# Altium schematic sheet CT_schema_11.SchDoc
size 742 x 377 mm
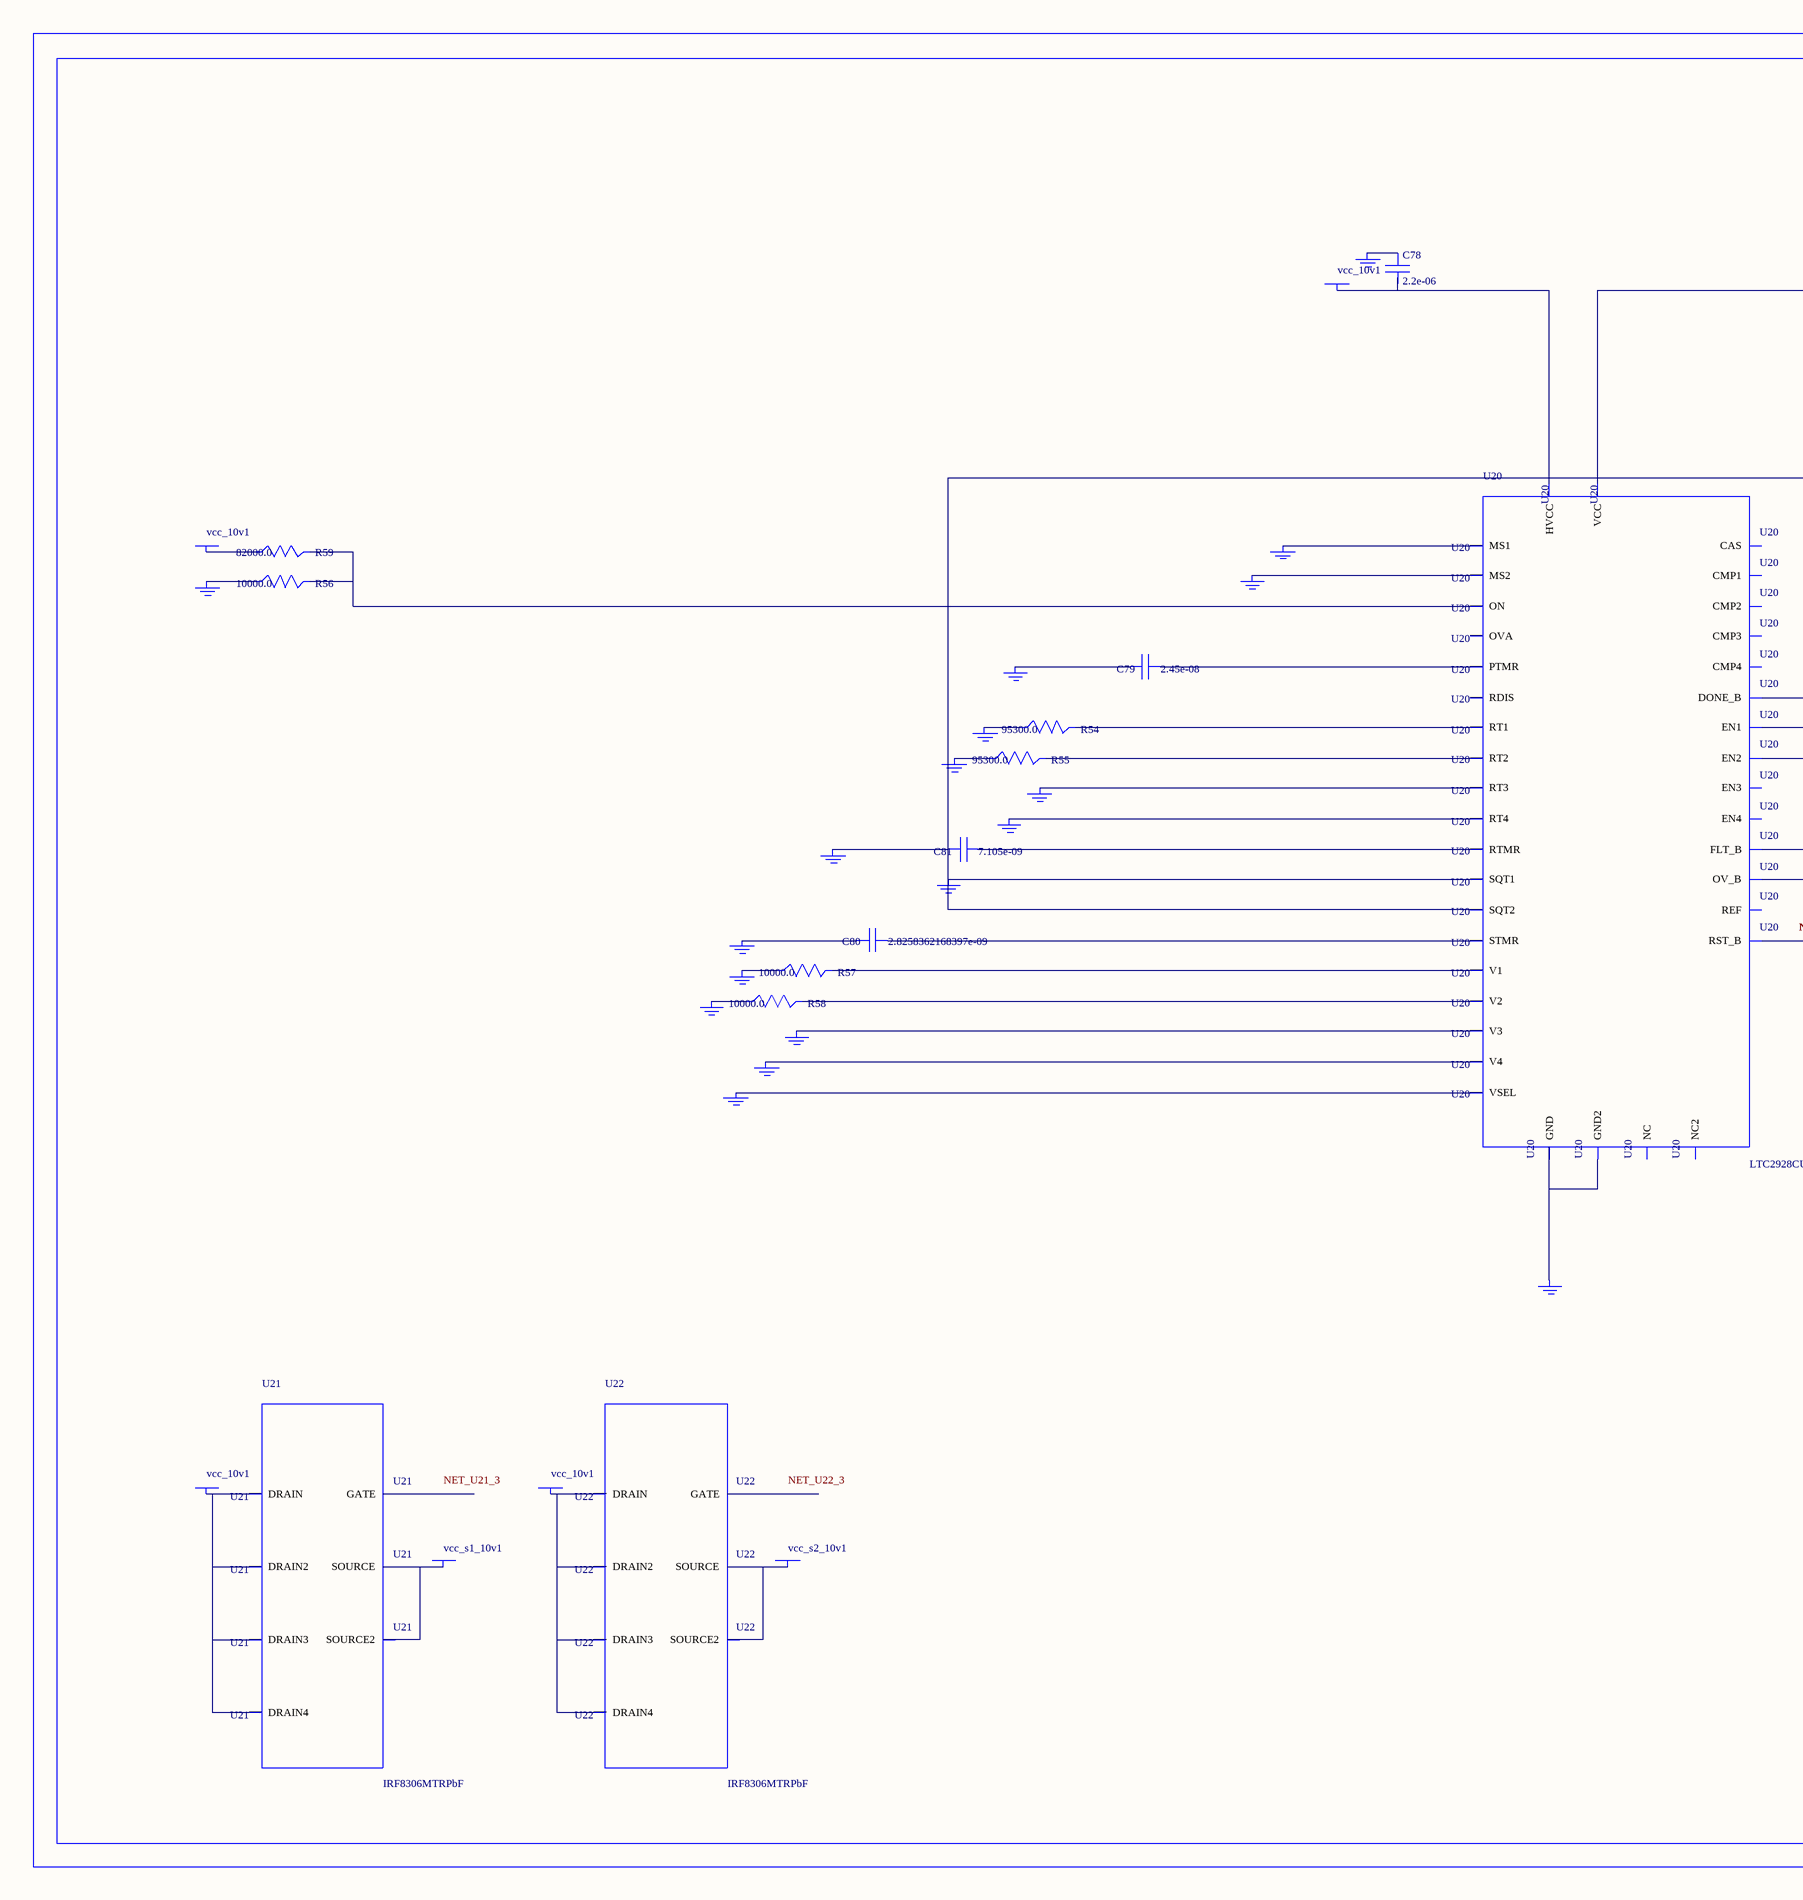
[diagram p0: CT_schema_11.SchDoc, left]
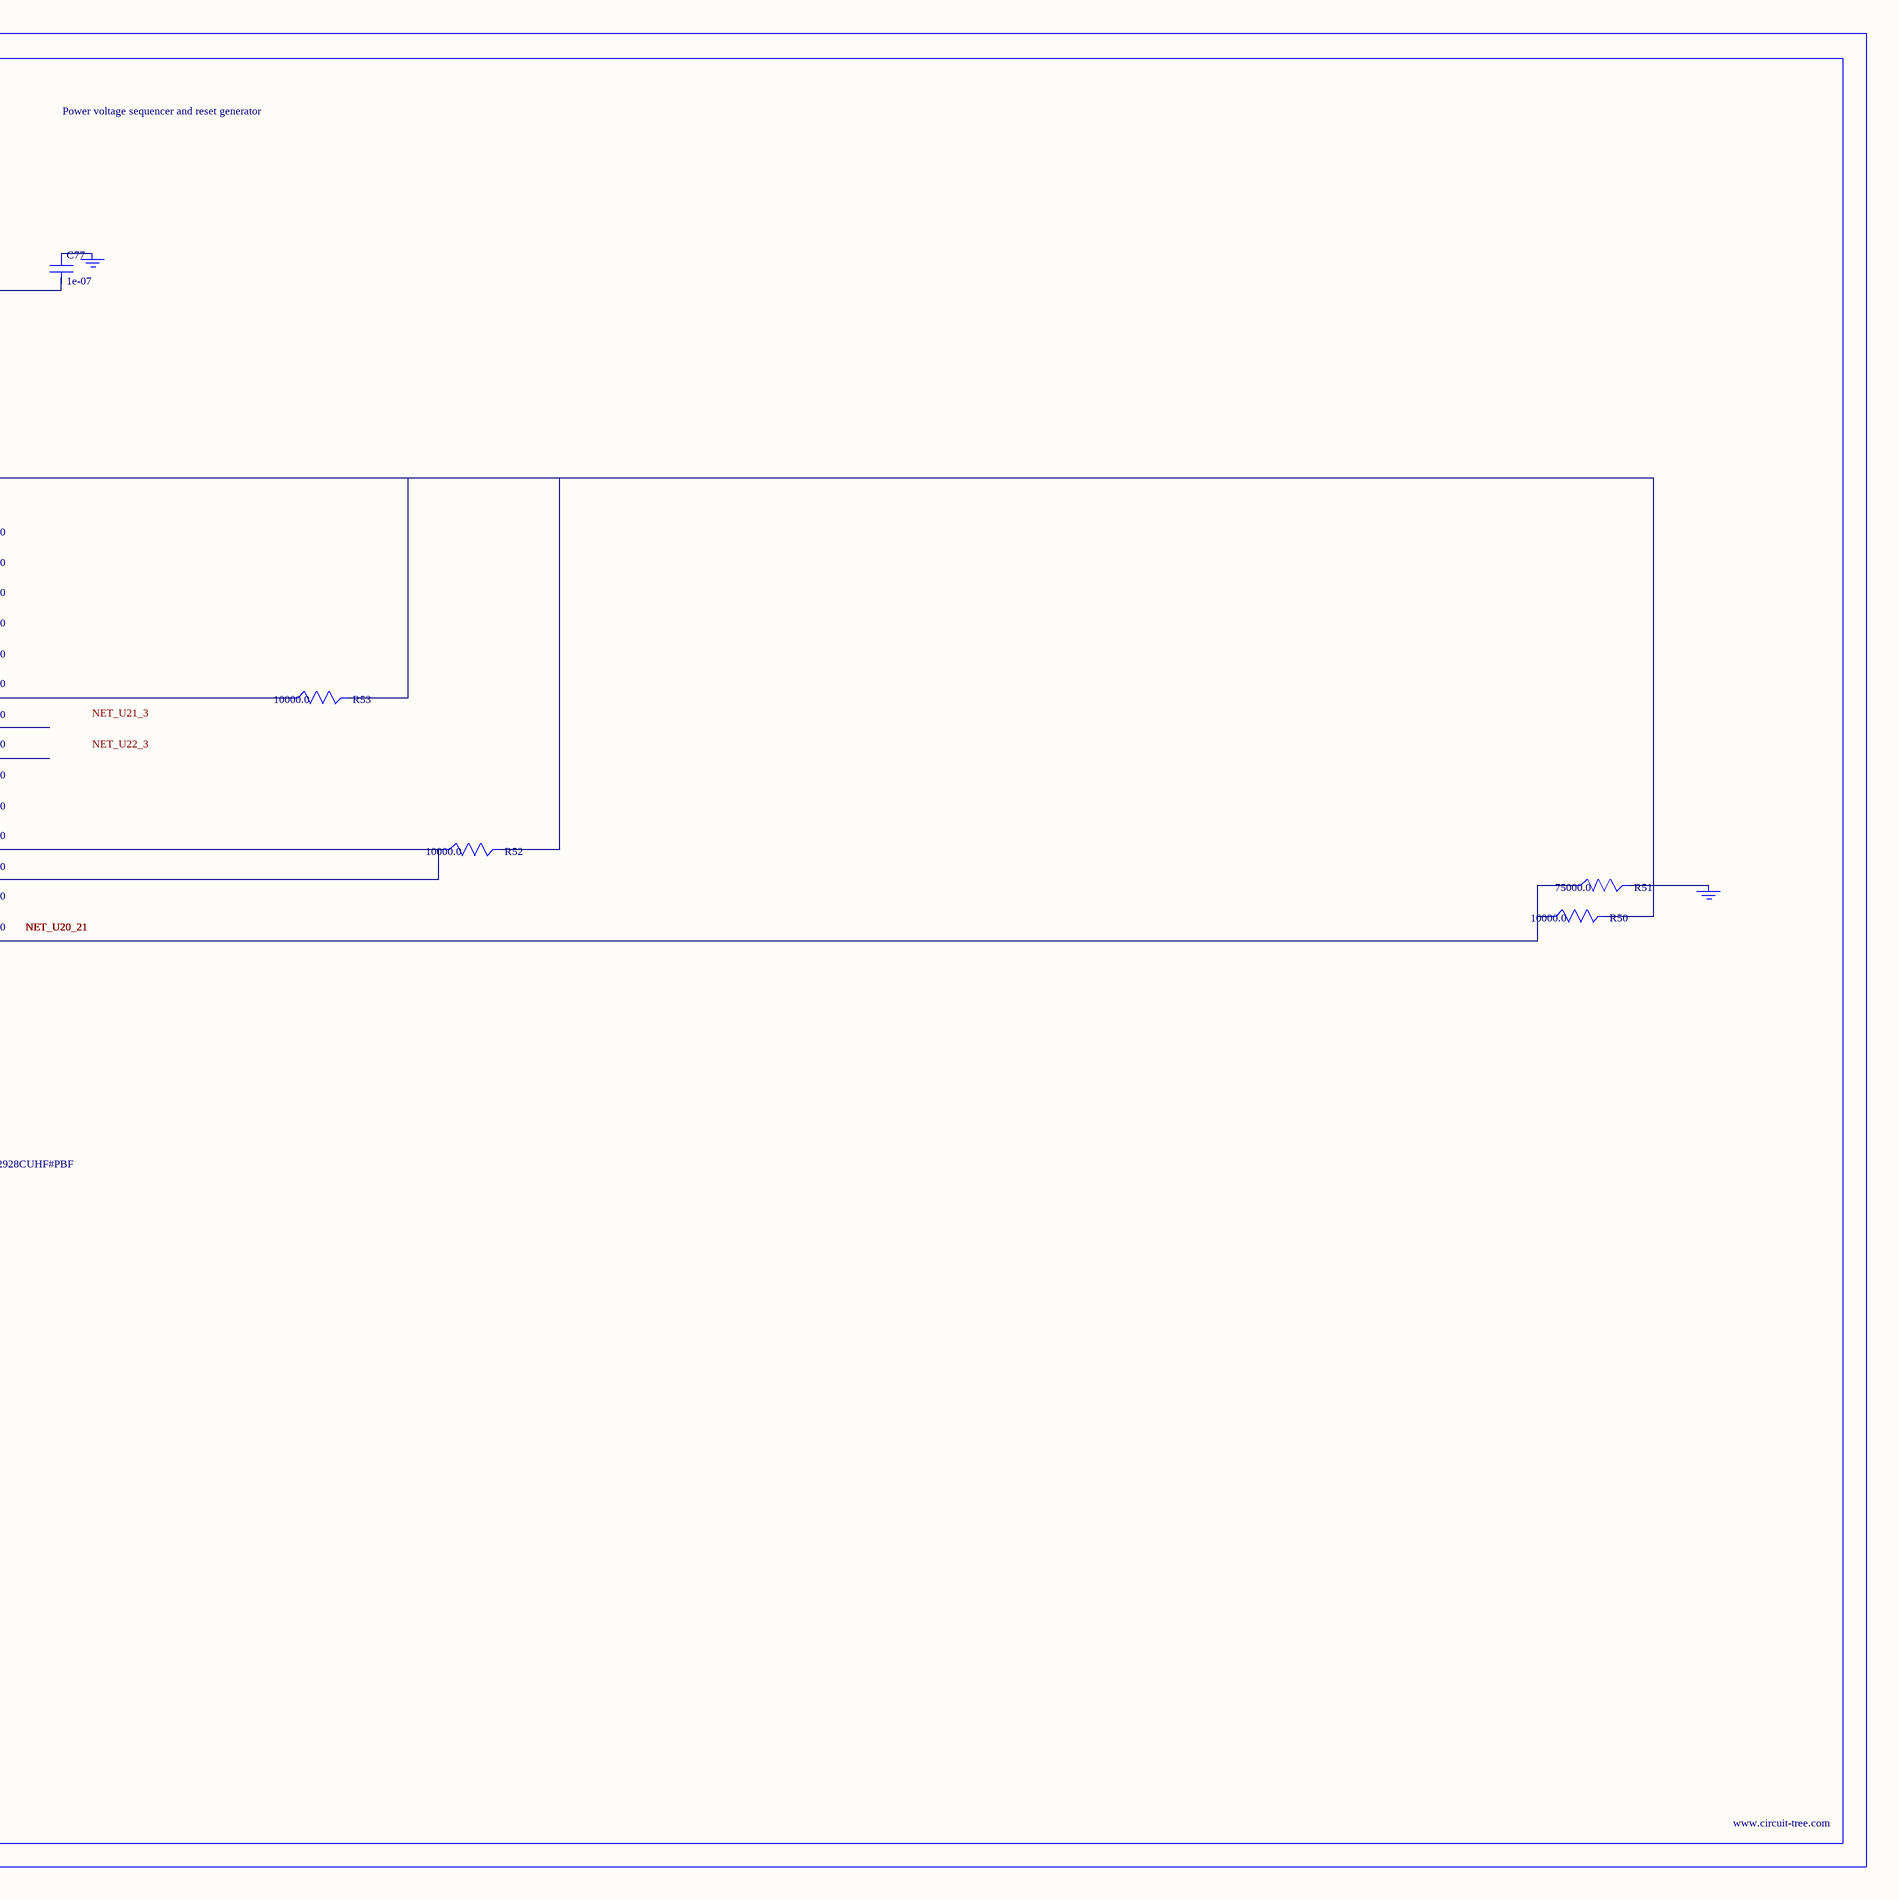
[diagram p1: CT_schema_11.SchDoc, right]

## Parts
BORDER10  (no value)
C77  1e-07  [C0402]
C78  2.2e-06  [C0603]
C79  2.45e-08  [R0603]
C80  2.8258362168397e-09  [R0603]
C81  7.105e-09  [R0603]
GND_INSTANCE_10_0  (no value)
GND_INSTANCE_10_1  (no value)
GND_INSTANCE_10_2  (no value)
GND_INSTANCE_10_3  (no value)
GND_INSTANCE_10_4  (no value)
GND_INSTANCE_10_5  (no value)
GND_INSTANCE_10_6  (no value)
GND_INSTANCE_10_7  (no value)
GND_INSTANCE_10_8  (no value)
GND_INSTANCE_10_9  (no value)
GND_INSTANCE_10_10  (no value)
GND_INSTANCE_10_11  (no value)
GND_INSTANCE_10_12  (no value)
GND_INSTANCE_10_13  (no value)
GND_INSTANCE_10_14  (no value)
GND_INSTANCE_10_15  (no value)
GND_INSTANCE_10_16  (no value)
GND_INSTANCE_10_17  (no value)
GND_INSTANCE_10_18  (no value)
GND_INSTANCE_10_19  (no value)
POWER_INSTANCE_10_0  vcc_10v1
POWER_INSTANCE_10_1  vcc_10v1
POWER_INSTANCE_10_2  vcc_10v1
POWER_INSTANCE_10_3  vcc_s1_10v1
POWER_INSTANCE_10_4  vcc_10v1
POWER_INSTANCE_10_5  vcc_s2_10v1
R50  10000.0  [R0603]
R51  75000.0  [R0603]
R52  10000.0  [R0603]
R53  10000.0  [R0603]
R54  95300.0  [R0603]
R55  95300.0  [R0603]
R56  10000.0  [R0603]
R57  10000.0  [R0603]
R58  10000.0  [R0603]
R59  82000.0  [R0603]
U20  LTC2928CUHF#PBF  [QFN-38_UHF]
U21  IRF8306MTRPbF  [IRF8306MTRPBF]
U22  IRF8306MTRPbF  [IRF8306MTRPBF]

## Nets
NetC77_1: C77.1 GND_INSTANCE_10_10.0(GND)
NetC77_2: C77.2 C81.2 GND_INSTANCE_10_5.0(GND) GND_INSTANCE_10_15.0(GND) R50.2 R52.2 R53.2 U20.10(SQT1) U20.11(SQT2) U20.22(VCC)
NetC78_1: C78.1 GND_INSTANCE_10_11.0(GND)
NetC78_2: C78.2 POWER_INSTANCE_10_1.0(PWR) U20.23(HVCC)
NetC79_1: C79.1 U20.27(PTMR)
NetC79_2: C79.2 GND_INSTANCE_10_14.0(GND)
NetC80_1: C80.1 U20.26(STMR)
NetC80_2: C80.2 GND_INSTANCE_10_13.0(GND)
NetC81_1: C81.1 U20.28(RTMR)
NetGND_INSTANCE_10_0_0: GND_INSTANCE_10_0.0(GND) R57.1
NetGND_INSTANCE_10_1_0: GND_INSTANCE_10_1.0(GND) R54.1
NetGND_INSTANCE_10_2_0: GND_INSTANCE_10_2.0(GND) R55.1
NetGND_INSTANCE_10_3_0: GND_INSTANCE_10_3.0(GND) U20.8(RT3)
NetGND_INSTANCE_10_4_0: GND_INSTANCE_10_4.0(GND) U20.9(RT4)
NetGND_INSTANCE_10_6_0: GND_INSTANCE_10_6.0(GND) U20.12(MS1)
NetGND_INSTANCE_10_7_0: GND_INSTANCE_10_7.0(GND) U20.13(MS2)
NetGND_INSTANCE_10_8_0: GND_INSTANCE_10_8.0(GND) R56.1
NetGND_INSTANCE_10_9_0: GND_INSTANCE_10_9.0(GND) R51.2
NetGND_INSTANCE_10_12_0: GND_INSTANCE_10_12.0(GND) U20.25(VSEL)
NetGND_INSTANCE_10_16_0: GND_INSTANCE_10_16.0(GND) U20.30(V4)
NetGND_INSTANCE_10_17_0: GND_INSTANCE_10_17.0(GND) U20.32(V3)
NetGND_INSTANCE_10_18_0: GND_INSTANCE_10_18.0(GND) R58.1
NetGND_INSTANCE_10_19_0: GND_INSTANCE_10_19.0(GND) U20.24(GND) U20.39(GND2)
NetPOWER_INSTANCE_10_0_0: POWER_INSTANCE_10_0.0(PWR) R59.1
NetPOWER_INSTANCE_10_2_0: POWER_INSTANCE_10_2.0(PWR) U21.1(DRAIN) U21.2(DRAIN2) U21.6(DRAIN3) U21.7(DRAIN4)
NetPOWER_INSTANCE_10_3_0: POWER_INSTANCE_10_3.0(PWR) U21.4(SOURCE) U21.5(SOURCE2)
NetPOWER_INSTANCE_10_4_0: POWER_INSTANCE_10_4.0(PWR) U22.1(DRAIN) U22.2(DRAIN2) U22.6(DRAIN3) U22.7(DRAIN4)
NetPOWER_INSTANCE_10_5_0: POWER_INSTANCE_10_5.0(PWR) U22.4(SOURCE) U22.5(SOURCE2)
NetR50_1: R50.1 R51.1 U20.21(RST_B)
NetR52_1: R52.1 U20.19(FLT_B) U20.20(OV_B)
NetR53_1: R53.1 U20.18(DONE_B)
NetR54_2: R54.2 U20.6(RT1)
NetR55_2: R55.2 U20.7(RT2)
NetR56_2: R56.2 R59.2 U20.16(ON)
NetR57_2: R57.2 U20.3(V1)
NetR58_2: R58.2 U20.38(V2)

Not connected (* = marked no-connect by the designer): U20 1(OVA) 2(EN1) 4(NC) 5(REF) 14(RDIS) 15(CAS) 17(NC2) 29(EN4) 31(EN3) 33(CMP3) 34(CMP4) 35(CMP1) 36(CMP2) 37(EN2); U21 3(GATE); U22 3(GATE)

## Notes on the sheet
- Labels drawn without touching a wire or pin: NET_U21_3, NET_U22_3

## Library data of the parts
BORDER10 = BORDER_PAGE10
C77 = C0402C104K3RACTU
C78 = GRM188R61H225KE1115D
C79 = C79
C80 = C80
C81 = C81
GND_INSTANCE_10_0-GND_INSTANCE_10_19 = GND
POWER_INSTANCE_10_0-POWER_INSTANCE_10_5 = PWR
R50 R52 R53 R56-R58 = RC0603JR-0710KL
R51 = RC0603JR-0775KL
R54 R55 = RC0603FR-0795K3L
R59 = RC0603JR-0782KL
